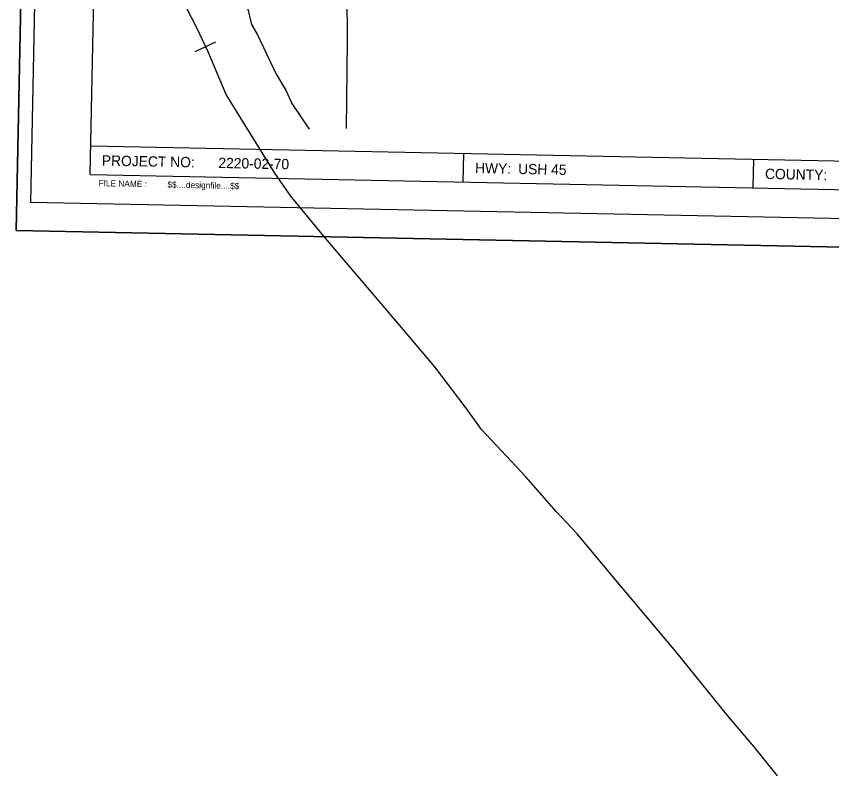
# Model space of a CAD drawing. Extents: x 331323 to 388339, y 121519 to 205315.
# Drawn here: x 354376 to 361475, y 121839 to 128453 of the extents above; entities that cross this region are included whole.
import ezdxf

# ---------------------------------------------------------------- set-up
doc = ezdxf.new("R2010")
doc.units = 0
for name, color, linetype in [('Level 1', 7, 'Continuous'), ('Level 2', 7, 'Continuous'), ('Level 4', 7, 'Continuous'), ('Level 5', 7, 'Continuous'), ('P_RDWY_Text', 7, 'Continuous'), ('PLT_Sheet_Border', 7, 'Continuous'), ('PLT_Sheet_Info', 7, 'Continuous')]:
    doc.layers.add(name, color=color, linetype=linetype)

msp = doc.modelspace()

# ---------------------------------------------------------------- linework, layer by layer
at = {"layer": 'Level 1'}
msp.add_line((360570.5, 122359.4), (360579.2, 122350.6), dxfattribs=at)
for points in [[(356203.5, 127771.7), (356045.3, 128142.2), (355947.1, 128351.4), (355766.9, 128703.1), (355668.9, 128929), (355578.9, 129113.1), (355431.6, 129422.8), (355081.1, 130179.4)], [(360579.2, 122350.6), (360570.5, 122359.4), (360117, 122921.9), (359597.3, 123543.3), (359259.1, 123946.3), (359077.4, 124139.6), (358813.3, 124442), (358425.2, 124853.9), (358293.4, 125038.4), (358021.5, 125399.2), (357600.8, 125894.7), (357064.5, 126524.6), (356767.6, 126885.6), (356627.7, 127086.9), (356331.8, 127564.6), (356203.5, 127771.7)], [(361004.8, 121839), (360801.6, 122090.6), (360570.5, 122359.4)]]:
    msp.add_lwpolyline(points, dxfattribs=at)
at = {"layer": 'Level 2'}
msp.add_lwpolyline([(355175.6, 131038.6), (355343.1, 130673.6), (355638.6, 130162.6), (356025.5, 129617.4), (356140.6, 129433), (356261.5, 128973.6), (356276.9, 128840.1), (356342, 128664.5), (356341.4, 128597.9), (356390.6, 128514.1), (356422.8, 128380.5), (356472, 128296.7), (356635.7, 127953.5), (356726, 127802.7), (356775.1, 127693.9), (356925.3, 127468.4)], dxfattribs=at)
at = {"layer": 'Level 4'}
msp.add_lwpolyline([(357241, 130321.4), (357255.5, 128239.6), (357248.4, 127474.7)], dxfattribs=at)
at = {"layer": 'Level 5'}
msp.add_line((355933.5, 128145.1), (356114.5, 128230), dxfattribs=at)
msp.add_lwpolyline([(356390, 127470.7), (356331.8, 127564.6), (356203.5, 127771.7), (356045.3, 128142.2), (355947.1, 128351.4), (355766.9, 128703.1), (355668.9, 128929), (355578.9, 129113.1), (355431.6, 129422.8), (355136.3, 130060.3)], dxfattribs=at)
at = {"layer": 'P_RDWY_Text'}
msp.add_lwpolyline([(354597.6, 137585.1), (371594.2, 137242.8), (371372.7, 126245), (354376.1, 126587.3)], close=True, dxfattribs=at)
at = {"layer": 'PLT_Sheet_Border'}
for points in [[(354376.1, 126587.3), (371372.7, 126245), (371594.2, 137242.8), (354597.6, 137585.1)], [(354501.1, 126834.8), (371047.8, 126501.6), (371259.2, 136999.5), (354712.6, 137332.7)]]:
    msp.add_lwpolyline(points, close=True, dxfattribs=at)
at = {"layer": 'PLT_Sheet_Info'}
for p, q in [((355018.6, 127074.5), (355219.9, 137072.4)), ((355023.6, 127324.4), (370770.4, 127007.3)), ((358267.9, 127009), (358273, 127259)), ((360792.4, 126958.2), (360797.4, 127208.1)), ((354376.1, 126587.3), (354386.2, 127087.2)), ((355018.6, 127074.5), (370765.4, 126757.3)), ((354376.1, 126587.3), (354876, 126577.2))]:
    msp.add_line(p, q, dxfattribs=at)

# ---------------------------------------------------------------- texts
for s, height, rotation, p in [('PROJECT NO:', 90, 358.84622, (355120.2, 127152.4)), ('2220-02-70', 90, 358.84622, (356135, 127132)), ('HWY:', 90, 358.84622, (358369.5, 127087)), ('USH 45          ', 90, 358.84622, (358744.4, 127079.4)), ('COUNTY:', 90, 358.84622, (360894, 127036.1)), ('FILE NAME :', 54, 358.84622, (355091.6, 126973)), ('$$....designfile....$$', 54, 358.84621, (355691.4, 126960.9))]:
    msp.add_text(s, height=height, rotation=rotation, dxfattribs=at).set_placement(p)

doc.saveas('drawing.dxf')
